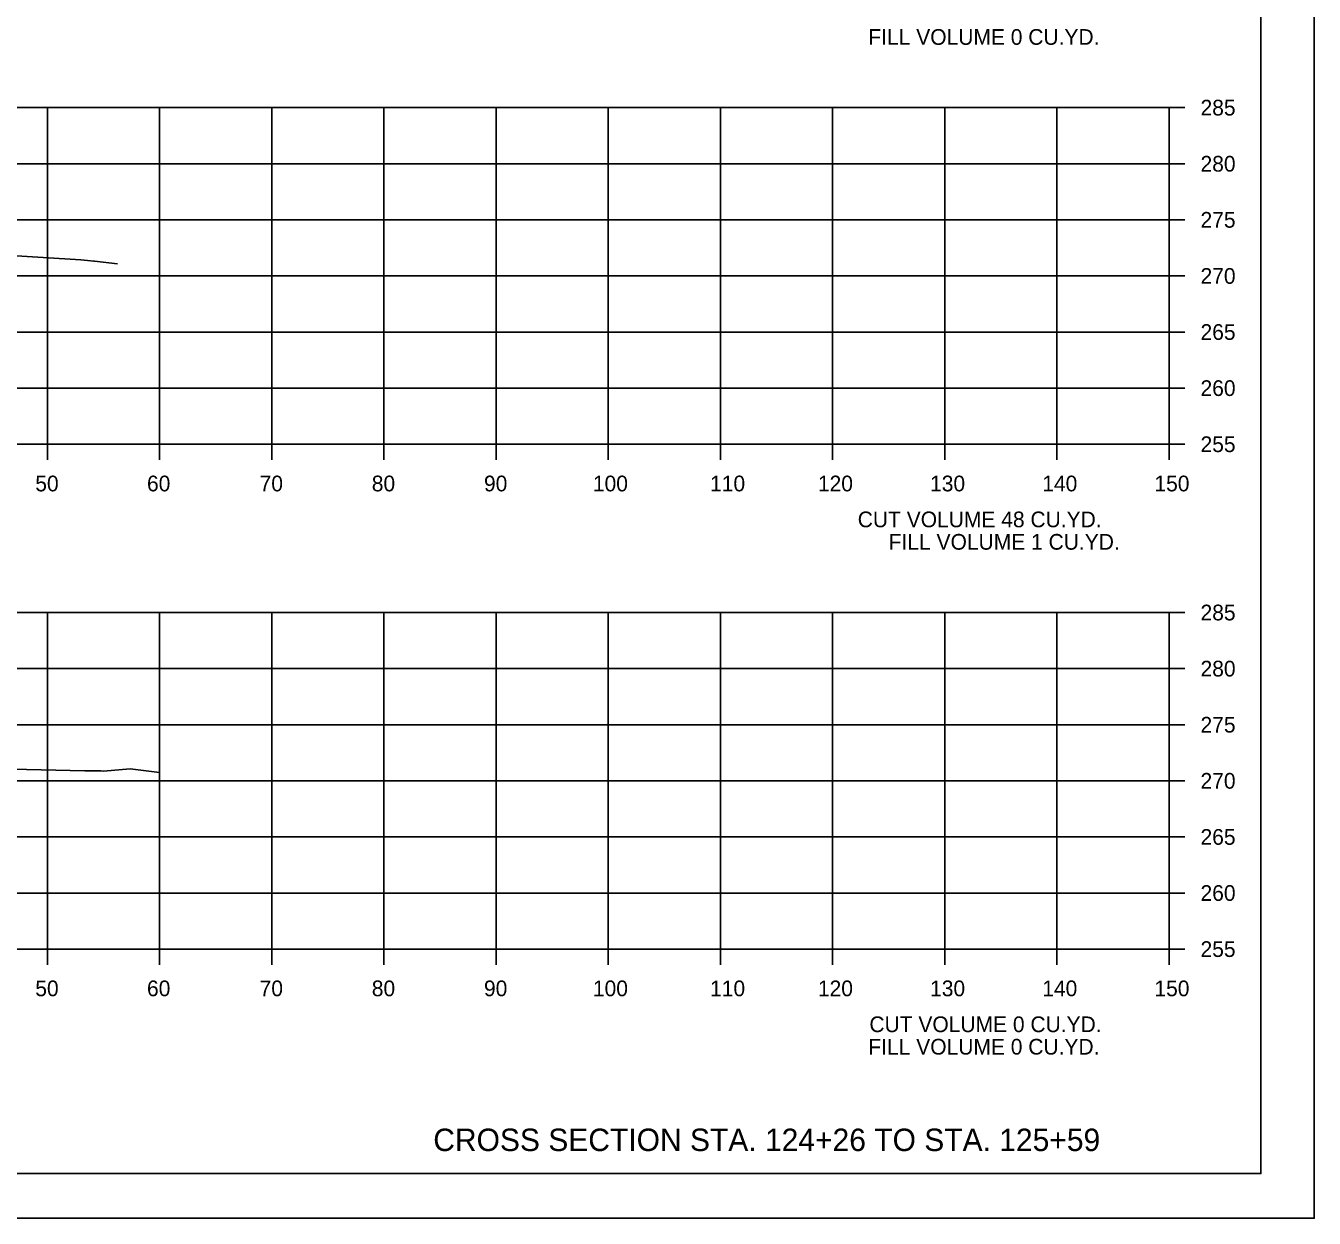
# Model space of a CAD drawing. Extents: x 1103485 to 1107180, y 2010593 to 2011873.
# Drawn here: x 1107065.3 to 1107180.1, y 2010592.8 to 2010699.1 of the extents above; entities that cross this region are included whole.
import ezdxf

# ---------------------------------------------------------------- set-up
doc = ezdxf.new("R2010")
doc.units = 0
for name, color, linetype in [('R_Axis', 7, 'Continuous'), ('R_Axis Annot', 7, 'Continuous'), ('R_Border', 7, 'Continuous'), ('R_Draft', 7, 'Continuous'), ('R_Exist Surface', 7, 'Continuous'), ('R_Grid', 7, 'Continuous'), ('R_No Plot', 7, 'Continuous')]:
    doc.layers.add(name, color=color, linetype=linetype)

msp = doc.modelspace()

# ---------------------------------------------------------------- linework, layer by layer
at = {"layer": 'R_Axis'}
for p, q in [((1107167.18, 2010661.82), (1107167.18, 2010691.82)), ((1107168.58, 2010691.82), (1107167.18, 2010691.82)), ((1107168.58, 2010686.82), (1107167.18, 2010686.82)), ((1107168.58, 2010681.82), (1107167.18, 2010681.82)), ((1107168.58, 2010676.82), (1107167.18, 2010676.82)), ((1107168.58, 2010671.82), (1107167.18, 2010671.82)), ((1107168.58, 2010666.82), (1107167.18, 2010666.82)), ((1106867.18, 2010661.82), (1107167.18, 2010661.82)), ((1107067.18, 2010660.42), (1107067.18, 2010661.82)), ((1107077.18, 2010660.42), (1107077.18, 2010661.82)), ((1107087.18, 2010660.42), (1107087.18, 2010661.82)), ((1107097.18, 2010660.42), (1107097.18, 2010661.82)), ((1107107.18, 2010660.42), (1107107.18, 2010661.82)), ((1107117.18, 2010660.42), (1107117.18, 2010661.82)), ((1107127.18, 2010660.42), (1107127.18, 2010661.82)), ((1107137.18, 2010660.42), (1107137.18, 2010661.82)), ((1107147.18, 2010660.42), (1107147.18, 2010661.82)), ((1107157.18, 2010660.42), (1107157.18, 2010661.82)), ((1107167.18, 2010660.42), (1107167.18, 2010661.82)), ((1107168.58, 2010661.82), (1107167.18, 2010661.82)), ((1107167.18, 2010616.82), (1107167.18, 2010646.82)), ((1107168.58, 2010646.82), (1107167.18, 2010646.82)), ((1107168.58, 2010641.82), (1107167.18, 2010641.82)), ((1107168.58, 2010636.82), (1107167.18, 2010636.82)), ((1107168.58, 2010631.82), (1107167.18, 2010631.82)), ((1107168.58, 2010626.82), (1107167.18, 2010626.82)), ((1107168.58, 2010621.82), (1107167.18, 2010621.82)), ((1106867.18, 2010616.82), (1107167.18, 2010616.82)), ((1107067.18, 2010615.42), (1107067.18, 2010616.82)), ((1107077.18, 2010615.42), (1107077.18, 2010616.82)), ((1107087.18, 2010615.42), (1107087.18, 2010616.82)), ((1107097.18, 2010615.42), (1107097.18, 2010616.82)), ((1107107.18, 2010615.42), (1107107.18, 2010616.82)), ((1107117.18, 2010615.42), (1107117.18, 2010616.82)), ((1107127.18, 2010615.42), (1107127.18, 2010616.82)), ((1107137.18, 2010615.42), (1107137.18, 2010616.82)), ((1107147.18, 2010615.42), (1107147.18, 2010616.82)), ((1107157.18, 2010615.42), (1107157.18, 2010616.82)), ((1107167.18, 2010615.42), (1107167.18, 2010616.82)), ((1107168.58, 2010616.82), (1107167.18, 2010616.82))]:
    msp.add_line(p, q, dxfattribs=at)
at = {"layer": 'R_Border'}
for q in [(1107175.36, 2010802.28), (1106859.18, 2010596.82)]:
    msp.add_line((1107175.36, 2010596.82), q, dxfattribs=at)
at = {"layer": 'R_Exist Surface'}
for points in [[(1107062.95, 2010678.71), (1107070.17, 2010678.25), (1107070.77, 2010678.21), (1107071.32, 2010678.14), (1107071.39, 2010678.13), (1107073.43, 2010677.89)], [(1107058.8, 2010632.98), (1107070.52, 2010632.72), (1107071.95, 2010632.7), (1107072.18, 2010632.69), (1107074.55, 2010632.88), (1107077.18, 2010632.57)]]:
    msp.add_lwpolyline(points, dxfattribs=at)
at = {"layer": 'R_Grid'}
for p, q in [((1106867.18, 2010691.82), (1107167.18, 2010691.82)), ((1107067.18, 2010661.82), (1107067.18, 2010691.82)), ((1107077.18, 2010661.82), (1107077.18, 2010691.82)), ((1107087.18, 2010661.82), (1107087.18, 2010691.82)), ((1107097.18, 2010661.82), (1107097.18, 2010691.82)), ((1107107.18, 2010661.82), (1107107.18, 2010691.82)), ((1107117.18, 2010661.82), (1107117.18, 2010691.82)), ((1107127.18, 2010661.82), (1107127.18, 2010691.82)), ((1107137.18, 2010661.82), (1107137.18, 2010691.82)), ((1107147.18, 2010661.82), (1107147.18, 2010691.82)), ((1107157.18, 2010661.82), (1107157.18, 2010691.82)), ((1107167.18, 2010661.82), (1107167.18, 2010691.82)), ((1106867.18, 2010686.82), (1107167.18, 2010686.82)), ((1106867.18, 2010681.82), (1107167.18, 2010681.82)), ((1106867.18, 2010676.82), (1107167.18, 2010676.82)), ((1106867.18, 2010671.82), (1107167.18, 2010671.82)), ((1106867.18, 2010666.82), (1107167.18, 2010666.82)), ((1106867.18, 2010661.82), (1107167.18, 2010661.82)), ((1106867.18, 2010646.82), (1107167.18, 2010646.82)), ((1107067.18, 2010616.82), (1107067.18, 2010646.82)), ((1107077.18, 2010616.82), (1107077.18, 2010646.82)), ((1107087.18, 2010616.82), (1107087.18, 2010646.82)), ((1107097.18, 2010616.82), (1107097.18, 2010646.82)), ((1107107.18, 2010616.82), (1107107.18, 2010646.82)), ((1107117.18, 2010616.82), (1107117.18, 2010646.82)), ((1107127.18, 2010616.82), (1107127.18, 2010646.82)), ((1107137.18, 2010616.82), (1107137.18, 2010646.82)), ((1107147.18, 2010616.82), (1107147.18, 2010646.82)), ((1107157.18, 2010616.82), (1107157.18, 2010646.82)), ((1107167.18, 2010616.82), (1107167.18, 2010646.82)), ((1106867.18, 2010641.82), (1107167.18, 2010641.82)), ((1106867.18, 2010636.82), (1107167.18, 2010636.82)), ((1106867.18, 2010631.82), (1107167.18, 2010631.82)), ((1106867.18, 2010626.82), (1107167.18, 2010626.82)), ((1106867.18, 2010621.82), (1107167.18, 2010621.82)), ((1106867.18, 2010616.82), (1107167.18, 2010616.82))]:
    msp.add_line(p, q, dxfattribs=at)
at = {"layer": 'R_No Plot'}
msp.add_line((1106846.78, 2010592.84), (1107180.12, 2010592.84), dxfattribs=at)
for points in [[(1106846.78, 2010806.17), (1107180.12, 2010806.17), (1107180.12, 2010592.83), (1106846.78, 2010592.83)], [(1107093.1, 2010802.28), (1107093.1, 2010792.4), (1107128.84, 2010792.4), (1107128.84, 2010789.48), (1107152.04, 2010789.48), (1107152.04, 2010765.14), (1107175.36, 2010765.14), (1107175.36, 2010596.82), (1106859.18, 2010596.82), (1106859.18, 2010802.28)]]:
    msp.add_lwpolyline(points, close=True, dxfattribs=at)

# ---------------------------------------------------------------- texts
at = {"layer": 'R_Axis Annot'}
for s, p in [('FILL VOLUME 0 CU.YD.', (1107140.37, 2010697.42)), ('285', (1107169.98, 2010691.12)), ('280', (1107169.98, 2010686.12)), ('275', (1107169.98, 2010681.12)), ('270', (1107169.98, 2010676.12)), ('265', (1107169.98, 2010671.12)), ('260', (1107169.98, 2010666.12)), ('255', (1107169.98, 2010661.12)), ('50', (1107066.1, 2010657.62)), ('60', (1107076.06, 2010657.62)), ('70', (1107086.1, 2010657.62)), ('80', (1107096.1, 2010657.62)), ('90', (1107106.1, 2010657.62)), ('100', (1107115.81, 2010657.62)), ('110', (1107126.26, 2010657.62)), ('120', (1107135.87, 2010657.62)), ('130', (1107145.87, 2010657.62)), ('140', (1107155.87, 2010657.62)), ('150', (1107165.87, 2010657.62)), ('CUT VOLUME 48 CU.YD.', (1107139.42, 2010654.42)), ('FILL VOLUME 1 CU.YD.', (1107142.18, 2010652.42)), ('285', (1107169.98, 2010646.12)), ('280', (1107169.98, 2010641.12)), ('275', (1107169.98, 2010636.12)), ('270', (1107169.98, 2010631.12)), ('265', (1107169.98, 2010626.12)), ('260', (1107169.98, 2010621.12)), ('255', (1107169.98, 2010616.12)), ('50', (1107066.1, 2010612.62)), ('60', (1107076.06, 2010612.62)), ('70', (1107086.1, 2010612.62)), ('80', (1107096.1, 2010612.62)), ('90', (1107106.1, 2010612.62)), ('100', (1107115.81, 2010612.62)), ('110', (1107126.26, 2010612.62)), ('120', (1107135.87, 2010612.62)), ('130', (1107145.87, 2010612.62)), ('140', (1107155.87, 2010612.62)), ('150', (1107165.87, 2010612.62)), ('CUT VOLUME 0 CU.YD.', (1107140.46, 2010609.42)), ('FILL VOLUME 0 CU.YD.', (1107140.37, 2010607.42))]:
    msp.add_text(s, height=1.4, dxfattribs=at).set_placement(p)
at = {"layer": 'R_Draft'}
msp.add_text('CROSS SECTION STA. 124+26 TO STA. 125+59', height=2, dxfattribs=at).set_placement((1107101.58, 2010598.82))

doc.saveas('drawing.dxf')
